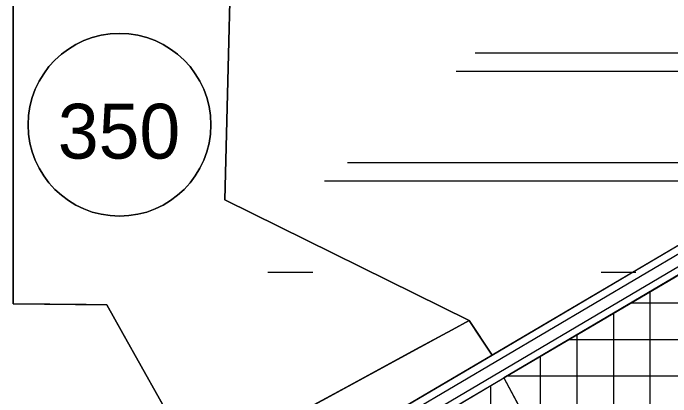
# Model space of a CAD drawing. Extents: x 427903 to 430077, y 4477233 to 4480385.
# Drawn here: x 428216.7 to 428396.6, y 4478157.8 to 4478262.8 of the extents above; entities that cross this region are included whole.
import ezdxf

# ---------------------------------------------------------------- set-up
doc = ezdxf.new("R2010")
doc.units = 0
for name, color, linetype in [('ADAKENARI', 7, 'Continuous'), ('KALDIRIM', 7, 'Continuous'), ('PL_K_TALI_IS_MRK', 7, 'Continuous'), ('PL_KON_MEV_350', 7, 'Continuous'), ('SM_DAIRE', 7, 'Continuous'), ('SM_TAKS', 7, 'Continuous'), ('TR_2_SITKORUMA', 7, 'Continuous'), ('TR_ORTAYOGUNKONUT', 7, 'Continuous'), ('TR_TALIISMERK', 7, 'Continuous')]:
    doc.layers.add(name, color=color, linetype=linetype)

msp = doc.modelspace()

# ---------------------------------------------------------------- linework, layer by layer
at = {"layer": 'ADAKENARI'}
for p, q in [((428216.73, 4478293.26), (428216.73, 4478183.18)), ((428350.94, 4478162.96), (428422, 4478204.89)), ((428402.49, 4478201.51), (428347.68, 4478169.16)), ((428216.73, 4478183.18), (428242.35, 4478182.94)), ((428242.35, 4478182.94), (428267.31, 4478138.36)), ((428267.31, 4478138.36), (428341.4, 4478178.64)), ((428341.4, 4478178.64), (428347.68, 4478169.16)), ((428347.68, 4478169.16), (428276.41, 4478127.24)), ((428347.68, 4478169.16), (428347.71, 4478169.11)), ((428297.31, 4478131.31), (428350.94, 4478162.96)), ((428350.94, 4478162.96), (428362.87, 4478140.68))]:
    msp.add_line(p, q, dxfattribs=at)
msp.add_lwpolyline([(428341.4, 4478178.64), (428274.62, 4478211.7), (428277.1, 4478309.36)], dxfattribs=at)
at = {"layer": 'KALDIRIM'}
for p, q in [((428284.74, 4478126.22), (428420.84, 4478206.53)), ((428280.22, 4478127.03), (428403.65, 4478199.87))]:
    msp.add_line(p, q, dxfattribs=at)
at = {"layer": 'PL_K_TALI_IS_MRK'}
for points in [[(428292.85, 4478330.03), (428296.45, 4478310.42), (428277.1, 4478309.36), (428274.62, 4478211.7), (428341.4, 4478178.64), (428344.62, 4478173.77), (428347.68, 4478169.16), (428402.49, 4478201.51), (428448.29, 4478240.18), (428401.88, 4478293.84), (428388.27, 4478307.62), (428410.61, 4478334.42), (428400.38, 4478339.16), (428384.62, 4478346.46), (428375.92, 4478350.49), (428396.66, 4478393.17), (428416.11, 4478423.81), (428407.55, 4478431.91), (428292.85, 4478330.03)], [(428256.89, 4478114.87), (428256.9, 4478114.88), (428256.9, 4478114.88), (428257.99, 4478116.06), (428258.32, 4478115.76), (428261.39, 4478113.06), (428279.53, 4478123.3), (428276.41, 4478127.24), (428269.36, 4478136.13), (428267.31, 4478138.36), (428266.73, 4478139.38), (428256.73, 4478157.25), (428246.73, 4478175.11), (428242.35, 4478182.94), (428236.73, 4478182.99), (428226.73, 4478183.09), (428216.73, 4478183.18), (428216.73, 4478293.26)], [(428422, 4478204.89), (428350.94, 4478162.96), (428362.87, 4478140.68), (428372.93, 4478138.26), (428386.2, 4478147.19), (428394.63, 4478133.93), (428400.94, 4478133.76)], [(428344.62, 4478173.77), (428341.4, 4478178.64), (428336.73, 4478176.1), (428326.73, 4478170.67), (428316.73, 4478165.23), (428306.73, 4478159.79), (428296.73, 4478154.35), (428286.73, 4478148.92), (428276.73, 4478143.48), (428267.31, 4478138.36), (428269.36, 4478136.13), (428276.41, 4478127.24), (428347.68, 4478169.16), (428344.62, 4478173.77)]]:
    msp.add_lwpolyline(points, dxfattribs=at)
msp.add_lwpolyline([(428350.94, 4478162.96), (428362.87, 4478140.68), (428372.93, 4478138.26), (428386.2, 4478147.19), (428394.63, 4478133.93), (428373.17, 4478121.09), (428364.42, 4478135.69), (428313.45, 4478104.76), (428303.54, 4478122.34), (428297.31, 4478131.31)], close=True, dxfattribs=at)
at = {"layer": 'PL_KON_MEV_350'}
msp.add_lwpolyline([(428216.73, 4478293.26), (428216.73, 4478183.18), (428226.73, 4478183.09), (428236.73, 4478182.99), (428242.35, 4478182.94), (428246.73, 4478175.11), (428256.73, 4478157.25), (428266.73, 4478139.38), (428267.31, 4478138.36), (428276.73, 4478143.48), (428286.73, 4478148.92), (428296.73, 4478154.35), (428306.73, 4478159.79), (428316.73, 4478165.23), (428326.73, 4478170.67), (428336.73, 4478176.1), (428341.4, 4478178.64), (428274.62, 4478211.7), (428277.1, 4478309.36)], dxfattribs=at)
at = {"layer": 'SM_DAIRE'}
msp.add_circle((428245.81, 4478232.21), 25, dxfattribs=at)
at = {"layer": 'TR_2_SITKORUMA'}
for p, q in [((428343.03, 4478251.9), (428467.39, 4478251.9)), ((428337.88, 4478246.9), (428461.27, 4478246.9)), ((428308.17, 4478221.9), (428431.3, 4478221.9)), ((428301.83, 4478216.9), (428425.51, 4478216.9)), ((428286.41, 4478191.9), (428298.65, 4478191.9)), ((428377.53, 4478191.9), (428386.97, 4478191.9))]:
    msp.add_line(p, q, dxfattribs=at)
at = {"layer": 'TR_ORTAYOGUNKONUT'}
msp.add_lwpolyline([(428216.73, 4478293.26), (428216.73, 4478183.18), (428226.73, 4478183.09), (428236.73, 4478182.99), (428242.35, 4478182.94), (428246.73, 4478175.11), (428256.73, 4478157.25), (428266.73, 4478139.38), (428267.31, 4478138.36), (428276.73, 4478143.48), (428286.73, 4478148.92), (428296.73, 4478154.35), (428306.73, 4478159.79), (428316.73, 4478165.23), (428326.73, 4478170.67), (428336.73, 4478176.1), (428341.4, 4478178.64), (428274.62, 4478211.7), (428277.1, 4478309.36)], dxfattribs=at)
for start, end in [(0, 180), (180, 0)]:
    msp.add_arc((428245.81, 4478232.21), 25, start, end, dxfattribs=at)
at = {"layer": 'TR_TALIISMERK'}
for p, q in [((428390.94, 4478139.73), (428390.94, 4478186.56)), ((428385.71, 4478183.48), (428582.26, 4478183.48)), ((428380.94, 4478143.65), (428380.94, 4478180.66)), ((428370.94, 4478138.74), (428370.94, 4478174.76)), ((428368.76, 4478173.48), (428573.29, 4478173.48)), ((428360.94, 4478144.29), (428360.94, 4478168.86)), ((428351.81, 4478163.48), (428564.33, 4478163.48)), ((428347.31, 4478125.31), (428347.31, 4478160.82))]:
    msp.add_line(p, q, dxfattribs=at)
for points in [[(428388.27, 4478307.62), (428410.61, 4478334.42), (428400.38, 4478339.16), (428384.62, 4478346.46), (428375.92, 4478350.49), (428396.66, 4478393.17), (428416.11, 4478423.81), (428407.55, 4478431.91), (428292.85, 4478330.03), (428296.45, 4478310.42), (428277.1, 4478309.36), (428274.62, 4478211.7), (428341.4, 4478178.64), (428344.62, 4478173.77), (428347.68, 4478169.16), (428402.49, 4478201.51), (428448.29, 4478240.18), (428401.88, 4478293.84), (428388.27, 4478307.62)], [(428256.73, 4478157.25), (428246.73, 4478175.11), (428242.35, 4478182.94), (428236.73, 4478182.99), (428226.73, 4478183.09), (428216.73, 4478183.18), (428216.73, 4478293.26)], [(428276.73, 4478143.48), (428267.31, 4478138.36), (428269.36, 4478136.13), (428276.41, 4478127.24), (428347.68, 4478169.16), (428344.62, 4478173.77), (428341.4, 4478178.64), (428336.73, 4478176.1), (428326.73, 4478170.67), (428316.73, 4478165.23), (428306.73, 4478159.79), (428296.73, 4478154.35), (428286.73, 4478148.92), (428276.73, 4478143.48)]]:
    msp.add_lwpolyline(points, dxfattribs=at)

# ---------------------------------------------------------------- texts
at = {"layer": 'SM_TAKS'}
msp.add_text('350', height=15, dxfattribs=at).set_placement((428228.95, 4478222.95))

doc.saveas('drawing.dxf')
